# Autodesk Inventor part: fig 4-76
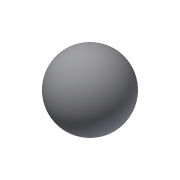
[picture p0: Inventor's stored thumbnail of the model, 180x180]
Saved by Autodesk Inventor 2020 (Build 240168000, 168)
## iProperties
Created: 2012-07
Part Number: fig 4-76
Material: Generic
Document SubType Name: Modeling
Designer: CADCIM
Density: 1 g/cm^3
Appearance: Default
Author: CADCIM
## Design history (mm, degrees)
feature "Form1"
body "Solid1"
body "Solid2"
